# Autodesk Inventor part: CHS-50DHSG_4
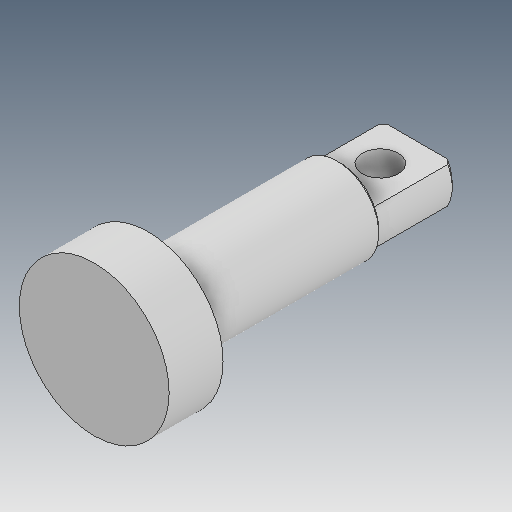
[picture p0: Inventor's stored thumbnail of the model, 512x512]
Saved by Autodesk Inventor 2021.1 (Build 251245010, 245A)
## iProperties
Created: 2019-04
Part Number: CHS-50DHSG_4
Material: Ogólny
Document SubType Name: Modeling
Designer: user
Density: 1 g/cm^3
Appearance: Domyślna
Author: user
Revision Number: ÈÎºÎ
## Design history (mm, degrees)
feature "ÊäÈë1"
node "Bryła1"
